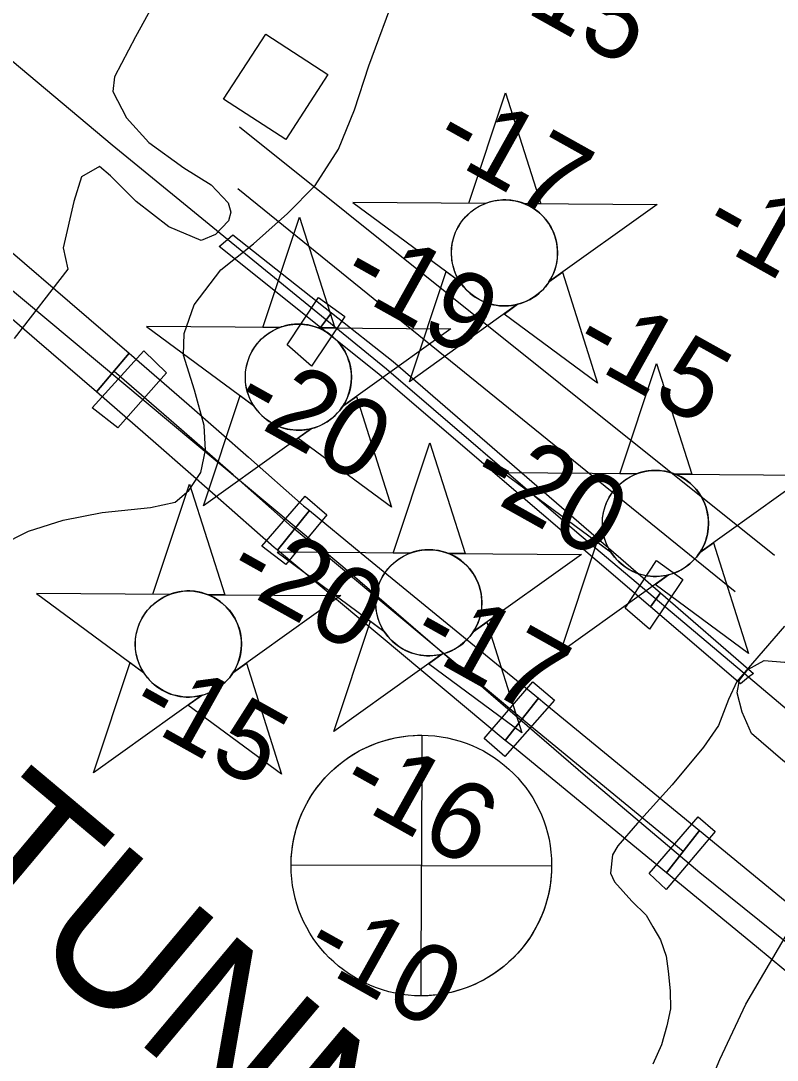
# Model space of a CAD drawing. Extents: x 3683402 to 3721514, y 487807 to 513565.
# Drawn here: x 3700378 to 3700814, y 501053 to 501651 of the extents above; entities that cross this region are included whole.
import ezdxf

# ---------------------------------------------------------------- set-up
doc = ezdxf.new("R2010")
doc.units = 0
for name, color, linetype in [('V-BLDG-OTLN', 7, 'Continuous'), ('V-BRDG-OTLN', 7, 'Continuous'), ('V-CHAN-DOCK', 7, 'Continuous'), ('V-CHAN-NAID', 7, 'Continuous'), ('V-LEVE-TOET', 7, 'Continuous'), ('V-RAIL-TRAK', 7, 'Continuous'), ('V-RIVR-GAGE', 7, 'Continuous'), ('V-ROAD-CNTR', 7, 'Continuous'), ('V-TOPO-GNAM-IDEN', 7, 'Continuous'), ('V-TOPO-SHOR', 7, 'Continuous'), ('V-TOPO-SPOT', 7, 'Continuous'), ('V-UTIL-LINE', 7, 'Continuous')]:
    doc.layers.add(name, color=color, linetype=linetype)

msp = doc.modelspace()

# ---------------------------------------------------------------- linework, layer by layer
at = {"layer": 'V-BLDG-OTLN'}
msp.add_lwpolyline([(3700494.92, 501606.31), (3700519.2, 501643.71), (3700554.98, 501620.48), (3700530.7, 501583.08)], close=True, dxfattribs=at)
at = {"layer": 'V-BRDG-OTLN'}
for points in [[(3700492.35, 501521.52), (3700497.16, 501525.65), (3700500.19, 501528.26), (3700557.09, 501483.31), (3700550.7, 501474.87)], [(3700550.7, 501474.87), (3700557.09, 501483.31), (3700592.49, 501455.36), (3700746.33, 501322.13), (3700740.52, 501314.23), (3700584.47, 501447.87)], [(3700421.7, 501437.84), (3700440.6, 501460.15), (3700475.12, 501430.13), (3700509.29, 501400.21), (3700540.85, 501372.36), (3700544.32, 501369.51), (3700525.89, 501346.66), (3700523.98, 501348.26), (3700489.98, 501378.25), (3700455.9, 501408.1)], [(3700525.89, 501346.66), (3700544.32, 501369.51), (3700574.07, 501345.02), (3700676.09, 501261.53), (3700657, 501237.26)], [(3700740.52, 501314.23), (3700746.33, 501322.13), (3700799.78, 501275.84), (3700796.96, 501273.56), (3700792.34, 501269.85)], [(3700657, 501237.26), (3700676.09, 501261.53), (3700679.76, 501258.52), (3700768.83, 501185.38), (3700749.72, 501161.07), (3700660.14, 501234.63)]]:
    msp.add_lwpolyline(points, close=True, dxfattribs=at)
for points in [[(3700372.01, 501519.15), (3700406.48, 501489.6), (3700440.6, 501460.15), (3700421.7, 501437.84), (3700387.42, 501467.43), (3700353.02, 501496.91)], [(3700759.4, 501173.39), (3700670.08, 501246.74), (3700534.35, 501360.02), (3700500.33, 501390.03), (3700466.21, 501419.91), (3700431.98, 501449.68), (3700431.83, 501449.81)], [(3700919.38, 501020.57), (3700880.2, 501053.24), (3700840.97, 501085.86), (3700801.69, 501118.4), (3700749.72, 501161.07), (3700768.83, 501185.38), (3700821.36, 501142.25), (3700860.71, 501109.65), (3700899.98, 501077), (3700939.2, 501044.29)]]:
    msp.add_lwpolyline(points, dxfattribs=at)
at = {"layer": 'V-CHAN-DOCK'}
for points in [[(3700531.56, 501464.88), (3700549.5, 501492.29), (3700564.66, 501481.28), (3700545.56, 501452.72)], [(3700433.96, 501417.1), (3700419.31, 501428.64), (3700448.93, 501461.42), (3700462.03, 501448.93)], [(3700530.66, 501338.46), (3700516.93, 501349.07), (3700541.89, 501377.78), (3700554.36, 501367.17)], [(3700726.04, 501313.43), (3700743.98, 501340.83), (3700759.14, 501329.83), (3700740.04, 501301.26)], [(3700644.84, 501238.36), (3700672.9, 501271.05), (3700685.37, 501260.44), (3700656.68, 501227.98)], [(3700739.75, 501160.62), (3700768.03, 501193.26), (3700777.81, 501184.78), (3700749.54, 501151.49)]]:
    msp.add_lwpolyline(points, close=True, dxfattribs=at)
at = {"layer": 'V-CHAN-NAID'}
for points in [[(3700645.69, 501546.4), (3700636.1, 501546.47), (3700657.23, 501609.95), (3700677.45, 501546.17), (3700667.86, 501546.24), (3700666.29, 501546.82), (3700664.19, 501547.44), (3700662.15, 501547.89), (3700660.12, 501548.2), (3700658.95, 501548.31), (3700657.42, 501548.39), (3700655.69, 501548.39), (3700654.32, 501548.32), (3700652.42, 501548.12), (3700651.05, 501547.9), (3700649.27, 501547.52), (3700647.74, 501547.1), (3700646.71, 501546.77)], [(3700645.69, 501546.4), (3700569.2, 501546.94), (3700630.76, 501501.54), (3700629.65, 501503.45), (3700628.84, 501505.08), (3700628.01, 501507.05), (3700627.32, 501509.1), (3700626.95, 501510.42), (3700626.59, 501512.05), (3700626.35, 501513.5), (3700626.16, 501515.09), (3700626.05, 501516.83), (3700626.04, 501518.41), (3700626.15, 501520.48), (3700626.33, 501522.1), (3700626.72, 501524.31), (3700627.2, 501526.23), (3700627.81, 501528.12), (3700628.46, 501529.79), (3700629.19, 501531.38), (3700630, 501532.92), (3700631.06, 501534.65), (3700632.09, 501536.12), (3700633.09, 501537.39), (3700634.1, 501538.54), (3700635.4, 501539.88), (3700636.46, 501540.84), (3700638.17, 501542.24), (3700639.38, 501543.11), (3700641.07, 501544.18), (3700642.8, 501545.12), (3700644.25, 501545.81)], [(3700667.86, 501546.24), (3700744.36, 501545.7), (3700682.15, 501501.18), (3700683.06, 501502.67), (3700684.04, 501504.51), (3700684.76, 501506.1), (3700685.5, 501508.05), (3700686.04, 501509.84), (3700686.44, 501511.48), (3700686.8, 501513.49), (3700686.99, 501515.06), (3700687.11, 501517.27), (3700687.08, 501519.33), (3700686.89, 501521.55), (3700686.63, 501523.31), (3700686.14, 501525.54), (3700685.5, 501527.68), (3700684.75, 501529.66), (3700684.1, 501531.1), (3700683.09, 501533.02), (3700682.03, 501534.74), (3700680.81, 501536.44), (3700679.55, 501537.98), (3700678.28, 501539.35), (3700676.65, 501540.88), (3700674.91, 501542.29), (3700673.22, 501543.47), (3700671.34, 501544.6), (3700669.86, 501545.36)], [(3700527.07, 501474.89), (3700517.48, 501474.96), (3700538.61, 501538.44), (3700558.83, 501474.66), (3700549.25, 501474.73), (3700547.67, 501475.31), (3700545.57, 501475.93), (3700543.53, 501476.38), (3700541.5, 501476.69), (3700540.33, 501476.8), (3700538.8, 501476.88), (3700537.08, 501476.88), (3700535.71, 501476.81), (3700533.8, 501476.61), (3700532.43, 501476.39), (3700530.65, 501476.01), (3700529.12, 501475.59), (3700528.09, 501475.26)], [(3700664.12, 501488.27), (3700601.92, 501443.75), (3700623.05, 501507.23), (3700630.76, 501501.54), (3700631.4, 501500.58), (3700632.78, 501498.72), (3700633.99, 501497.3), (3700635.46, 501495.8), (3700636.85, 501494.55), (3700638.3, 501493.39), (3700639.71, 501492.41), (3700641.38, 501491.37), (3700643.1, 501490.46), (3700644.89, 501489.65), (3700646.33, 501489.09), (3700647.96, 501488.56), (3700650.19, 501488), (3700651.72, 501487.71), (3700653.75, 501487.46), (3700655.28, 501487.35), (3700657.14, 501487.33), (3700658.83, 501487.41), (3700660.54, 501487.58), (3700662.44, 501487.89)], [(3700682.15, 501501.18), (3700689.95, 501506.76), (3700710.17, 501442.98), (3700656.33, 501482.69), (3700664.12, 501488.27), (3700665.79, 501488.75), (3700667.4, 501489.31), (3700669.56, 501490.22), (3700671.29, 501491.11), (3700673.16, 501492.22), (3700674.9, 501493.43), (3700676.45, 501494.68), (3700677.74, 501495.84), (3700679.12, 501497.26), (3700680.33, 501498.67), (3700681.44, 501500.14)], [(3700527.07, 501474.89), (3700450.58, 501475.43), (3700512.14, 501430.03), (3700511.03, 501431.94), (3700510.22, 501433.57), (3700509.4, 501435.54), (3700508.7, 501437.59), (3700508.34, 501438.91), (3700507.97, 501440.54), (3700507.73, 501441.98), (3700507.54, 501443.58), (3700507.43, 501445.32), (3700507.42, 501446.9), (3700507.53, 501448.97), (3700507.71, 501450.59), (3700508.1, 501452.79), (3700508.58, 501454.72), (3700509.19, 501456.6), (3700509.84, 501458.28), (3700510.57, 501459.87), (3700511.38, 501461.41), (3700512.44, 501463.14), (3700513.48, 501464.61), (3700514.48, 501465.88), (3700515.48, 501467.03), (3700516.79, 501468.36), (3700517.84, 501469.33), (3700519.55, 501470.73), (3700520.77, 501471.6), (3700522.45, 501472.67), (3700524.18, 501473.61), (3700525.63, 501474.3)], [(3700549.25, 501474.73), (3700625.74, 501474.19), (3700563.54, 501429.67), (3700564.45, 501431.15), (3700565.42, 501433), (3700566.14, 501434.59), (3700566.88, 501436.54), (3700567.42, 501438.33), (3700567.82, 501439.97), (3700568.18, 501441.98), (3700568.37, 501443.55), (3700568.49, 501445.75), (3700568.46, 501447.82), (3700568.27, 501450.04), (3700568.01, 501451.79), (3700567.52, 501454.03), (3700566.88, 501456.17), (3700566.13, 501458.15), (3700565.48, 501459.59), (3700564.47, 501461.51), (3700563.41, 501463.23), (3700562.2, 501464.93), (3700560.94, 501466.47), (3700559.66, 501467.84), (3700558.03, 501469.37), (3700556.29, 501470.78), (3700554.61, 501471.96), (3700552.72, 501473.09), (3700551.25, 501473.85)], [(3700732.56, 501390.7), (3700722.97, 501390.77), (3700744.1, 501454.26), (3700764.32, 501390.48), (3700754.73, 501390.55), (3700753.16, 501391.13), (3700751.06, 501391.75), (3700749.02, 501392.2), (3700746.98, 501392.5), (3700745.82, 501392.62), (3700744.28, 501392.7), (3700742.56, 501392.7), (3700741.19, 501392.63), (3700739.29, 501392.43), (3700737.92, 501392.21), (3700736.14, 501391.82), (3700734.61, 501391.4), (3700733.57, 501391.07)], [(3700545.5, 501416.76), (3700483.3, 501372.24), (3700504.43, 501435.72), (3700512.14, 501430.03), (3700512.78, 501429.07), (3700514.16, 501427.21), (3700515.38, 501425.79), (3700516.84, 501424.29), (3700518.23, 501423.04), (3700519.68, 501421.88), (3700521.09, 501420.89), (3700522.77, 501419.86), (3700524.48, 501418.95), (3700526.27, 501418.14), (3700527.72, 501417.58), (3700529.34, 501417.05), (3700531.57, 501416.49), (3700533.1, 501416.2), (3700535.13, 501415.94), (3700536.66, 501415.84), (3700538.53, 501415.82), (3700540.21, 501415.9), (3700541.92, 501416.07), (3700543.83, 501416.38)], [(3700563.54, 501429.67), (3700571.33, 501435.25), (3700591.56, 501371.47), (3700537.71, 501411.18), (3700545.5, 501416.76), (3700547.17, 501417.24), (3700548.78, 501417.8), (3700550.94, 501418.71), (3700552.68, 501419.59), (3700554.54, 501420.71), (3700556.28, 501421.92), (3700557.83, 501423.16), (3700559.12, 501424.33), (3700560.5, 501425.75), (3700561.71, 501427.15), (3700562.83, 501428.63)], [(3700602.13, 501345.03), (3700592.54, 501345.1), (3700613.67, 501408.59), (3700633.89, 501344.81), (3700624.31, 501344.88), (3700622.73, 501345.46), (3700620.63, 501346.08), (3700618.59, 501346.53), (3700616.56, 501346.83), (3700615.39, 501346.95), (3700613.86, 501347.03), (3700612.14, 501347.03), (3700610.77, 501346.96), (3700608.86, 501346.76), (3700607.49, 501346.54), (3700605.71, 501346.15), (3700604.18, 501345.73), (3700603.15, 501345.4)], [(3700732.56, 501390.7), (3700656.07, 501391.25), (3700717.63, 501345.85), (3700716.52, 501347.76), (3700715.71, 501349.38), (3700714.88, 501351.35), (3700714.19, 501353.41), (3700713.82, 501354.73), (3700713.46, 501356.36), (3700713.22, 501357.8), (3700713.03, 501359.4), (3700712.92, 501361.13), (3700712.91, 501362.72), (3700713.01, 501364.79), (3700713.2, 501366.41), (3700713.59, 501368.61), (3700714.07, 501370.53), (3700714.67, 501372.42), (3700715.33, 501374.1), (3700716.06, 501375.69), (3700716.87, 501377.22), (3700717.93, 501378.96), (3700718.96, 501380.43), (3700719.96, 501381.7), (3700720.96, 501382.84), (3700722.27, 501384.18), (3700723.32, 501385.15), (3700725.04, 501386.54), (3700726.25, 501387.41), (3700727.94, 501388.48), (3700729.67, 501389.43), (3700731.12, 501390.11)], [(3700754.73, 501390.55), (3700831.22, 501390), (3700769.02, 501345.48), (3700769.93, 501346.97), (3700770.91, 501348.82), (3700771.63, 501350.4), (3700772.36, 501352.36), (3700772.91, 501354.14), (3700773.31, 501355.78), (3700773.67, 501357.79), (3700773.85, 501359.37), (3700773.98, 501361.57), (3700773.95, 501363.63), (3700773.76, 501365.85), (3700773.49, 501367.61), (3700773, 501369.84), (3700772.36, 501371.98), (3700771.61, 501373.97), (3700770.97, 501375.41), (3700769.96, 501377.32), (3700768.9, 501379.05), (3700767.68, 501380.75), (3700766.42, 501382.29), (3700765.15, 501383.65), (3700763.52, 501385.19), (3700761.77, 501386.6), (3700760.09, 501387.77), (3700758.2, 501388.91), (3700756.73, 501389.67)], [(3700463.76, 501321.27), (3700454.17, 501321.34), (3700475.3, 501384.82), (3700495.52, 501321.04), (3700485.94, 501321.11), (3700484.36, 501321.69), (3700482.26, 501322.31), (3700480.22, 501322.76), (3700478.19, 501323.07), (3700477.02, 501323.18), (3700475.49, 501323.26), (3700473.76, 501323.26), (3700472.39, 501323.19), (3700470.49, 501322.99), (3700469.12, 501322.77), (3700467.34, 501322.39), (3700465.81, 501321.97), (3700464.78, 501321.64)], [(3700750.99, 501332.58), (3700688.79, 501288.05), (3700709.91, 501351.54), (3700717.63, 501345.85), (3700718.27, 501344.88), (3700719.65, 501343.02), (3700720.86, 501341.61), (3700722.33, 501340.11), (3700723.72, 501338.85), (3700725.17, 501337.7), (3700726.57, 501336.71), (3700728.25, 501335.68), (3700729.97, 501334.76), (3700731.76, 501333.95), (3700733.2, 501333.4), (3700734.83, 501332.87), (3700737.06, 501332.3), (3700738.59, 501332.02), (3700740.61, 501331.76), (3700742.15, 501331.66), (3700744.01, 501331.63), (3700745.7, 501331.71), (3700747.41, 501331.89), (3700749.31, 501332.2)], [(3700769.02, 501345.48), (3700776.82, 501351.06), (3700797.04, 501287.29), (3700743.19, 501327), (3700750.99, 501332.58), (3700752.66, 501333.05), (3700754.27, 501333.61), (3700756.43, 501334.53), (3700758.16, 501335.41), (3700760.03, 501336.52), (3700761.77, 501337.74), (3700763.32, 501338.98), (3700764.61, 501340.15), (3700765.99, 501341.57), (3700767.19, 501342.97), (3700768.31, 501344.44)], [(3700602.13, 501345.03), (3700525.64, 501345.58), (3700587.2, 501300.18), (3700586.09, 501302.09), (3700585.28, 501303.71), (3700584.46, 501305.68), (3700583.76, 501307.74), (3700583.4, 501309.06), (3700583.03, 501310.69), (3700582.79, 501312.13), (3700582.6, 501313.73), (3700582.49, 501315.46), (3700582.48, 501317.05), (3700582.59, 501319.12), (3700582.77, 501320.74), (3700583.16, 501322.94), (3700583.64, 501324.86), (3700584.25, 501326.75), (3700584.9, 501328.43), (3700585.63, 501330.02), (3700586.44, 501331.55), (3700587.5, 501333.29), (3700588.54, 501334.76), (3700589.54, 501336.03), (3700590.54, 501337.17), (3700591.85, 501338.51), (3700592.9, 501339.48), (3700594.61, 501340.87), (3700595.83, 501341.74), (3700597.51, 501342.81), (3700599.24, 501343.76), (3700600.69, 501344.44)], [(3700624.31, 501344.88), (3700700.8, 501344.33), (3700638.6, 501299.81), (3700639.51, 501301.3), (3700640.48, 501303.15), (3700641.2, 501304.73), (3700641.94, 501306.69), (3700642.48, 501308.47), (3700642.88, 501310.11), (3700643.24, 501312.12), (3700643.43, 501313.7), (3700643.55, 501315.9), (3700643.52, 501317.96), (3700643.33, 501320.18), (3700643.07, 501321.94), (3700642.58, 501324.17), (3700641.94, 501326.31), (3700641.19, 501328.3), (3700640.54, 501329.74), (3700639.53, 501331.65), (3700638.47, 501333.38), (3700637.26, 501335.08), (3700636, 501336.62), (3700634.72, 501337.98), (3700633.09, 501339.52), (3700631.35, 501340.93), (3700629.67, 501342.1), (3700627.78, 501343.24), (3700626.31, 501344)], [(3700463.76, 501321.27), (3700387.27, 501321.81), (3700448.83, 501276.41), (3700447.72, 501278.32), (3700446.91, 501279.95), (3700446.09, 501281.92), (3700445.39, 501283.97), (3700445.02, 501285.29), (3700444.66, 501286.92), (3700444.42, 501288.37), (3700444.23, 501289.96), (3700444.12, 501291.7), (3700444.11, 501293.28), (3700444.22, 501295.35), (3700444.4, 501296.97), (3700444.79, 501299.18), (3700445.27, 501301.1), (3700445.88, 501302.99), (3700446.53, 501304.66), (3700447.26, 501306.25), (3700448.07, 501307.79), (3700449.13, 501309.52), (3700450.16, 501310.99), (3700451.16, 501312.26), (3700452.17, 501313.41), (3700453.48, 501314.75), (3700454.53, 501315.71), (3700456.24, 501317.11), (3700457.46, 501317.98), (3700459.14, 501319.05), (3700460.87, 501319.99), (3700462.32, 501320.68)], [(3700485.94, 501321.11), (3700562.43, 501320.57), (3700500.22, 501276.05), (3700501.14, 501277.54), (3700502.11, 501279.38), (3700502.83, 501280.97), (3700503.57, 501282.92), (3700504.11, 501284.71), (3700504.51, 501286.35), (3700504.87, 501288.36), (3700505.06, 501289.93), (3700505.18, 501292.14), (3700505.15, 501294.2), (3700504.96, 501296.42), (3700504.7, 501298.18), (3700504.21, 501300.41), (3700503.57, 501302.55), (3700502.82, 501304.53), (3700502.17, 501305.97), (3700501.16, 501307.89), (3700500.1, 501309.61), (3700498.89, 501311.31), (3700497.62, 501312.85), (3700496.35, 501314.22), (3700494.72, 501315.75), (3700492.98, 501317.16), (3700491.29, 501318.34), (3700489.41, 501319.47), (3700487.94, 501320.23)], [(3700620.56, 501286.91), (3700558.36, 501242.38), (3700579.49, 501305.87), (3700587.2, 501300.18), (3700587.84, 501299.21), (3700589.22, 501297.35), (3700590.44, 501295.94), (3700591.9, 501294.44), (3700593.29, 501293.18), (3700594.74, 501292.03), (3700596.15, 501291.04), (3700597.83, 501290.01), (3700599.54, 501289.09), (3700601.33, 501288.28), (3700602.78, 501287.73), (3700604.4, 501287.2), (3700606.63, 501286.63), (3700608.16, 501286.35), (3700610.19, 501286.09), (3700611.72, 501285.99), (3700613.59, 501285.96), (3700615.27, 501286.04), (3700616.98, 501286.22), (3700618.89, 501286.53)], [(3700638.6, 501299.81), (3700646.39, 501305.39), (3700666.62, 501241.62), (3700612.77, 501281.33), (3700620.56, 501286.91), (3700622.23, 501287.38), (3700623.84, 501287.94), (3700626, 501288.86), (3700627.74, 501289.74), (3700629.6, 501290.85), (3700631.34, 501292.07), (3700632.89, 501293.31), (3700634.18, 501294.48), (3700635.56, 501295.9), (3700636.77, 501297.3), (3700637.89, 501298.77)], [(3700482.19, 501263.14), (3700419.99, 501218.62), (3700441.12, 501282.1), (3700448.83, 501276.41), (3700449.47, 501275.45), (3700450.85, 501273.59), (3700452.06, 501272.17), (3700453.53, 501270.67), (3700454.92, 501269.42), (3700456.37, 501268.26), (3700457.78, 501267.28), (3700459.45, 501266.24), (3700461.17, 501265.33), (3700462.96, 501264.52), (3700464.41, 501263.96), (3700466.03, 501263.43), (3700468.26, 501262.87), (3700469.79, 501262.58), (3700471.82, 501262.33), (3700473.35, 501262.22), (3700475.21, 501262.2), (3700476.9, 501262.28), (3700478.61, 501262.45), (3700480.52, 501262.76)], [(3700500.22, 501276.05), (3700508.02, 501281.63), (3700528.24, 501217.85), (3700474.4, 501257.56), (3700482.19, 501263.14), (3700483.86, 501263.62), (3700485.47, 501264.18), (3700487.63, 501265.09), (3700489.36, 501265.98), (3700491.23, 501267.09), (3700492.97, 501268.3), (3700494.52, 501269.55), (3700495.81, 501270.71), (3700497.19, 501272.13), (3700498.4, 501273.54), (3700499.52, 501275.01)]]:
    msp.add_lwpolyline(points, close=True, dxfattribs=at)
for centre in [(3700656.57, 501517.86), (3700537.96, 501446.35), (3700743.44, 501362.17), (3700613.02, 501316.5), (3700474.64, 501292.74)]:
    msp.add_circle(centre, 30.54, dxfattribs=at)
at = {"layer": 'V-LEVE-TOET'}
for points in [[(3700773.66, 501037.06), (3700780.42, 501053.65), (3700795.41, 501085.36), (3700829.8, 501143.94), (3700850.12, 501182), (3700848.13, 501195.15), (3700837.36, 501210.7), (3700816.85, 501225.73), (3700798.77, 501241.26), (3700793.37, 501253.42), (3700790.41, 501264.61), (3700791.86, 501271.93), (3700796.56, 501278.07), (3700805.94, 501283.18), (3700817.63, 501282.24), (3700837.62, 501275.49), (3700858.13, 501263.38), (3700874.23, 501254.67), (3700886.39, 501260.07), (3700898.52, 501275.7), (3700941.07, 501365.97), (3701009.36, 501481.17), (3701075.15, 501616.33), (3701142.42, 501744.68)], [(3700496.95, 501741.56), (3700468.18, 501686.01), (3700444.28, 501642.24), (3700432.1, 501619.14), (3700431.14, 501610.79), (3700439.05, 501595.6), (3700451.86, 501581.42), (3700472.03, 501566.76), (3700487.77, 501557), (3700497.62, 501546.73), (3700499.11, 501541.34), (3700497.65, 501536.42), (3700490.32, 501528.55), (3700481.99, 501525.08), (3700463.31, 501532.87), (3700444.61, 501547.53), (3700429.84, 501562.2), (3700423.44, 501567.58), (3700413.15, 501561.65), (3700408.78, 501547.4), (3700402.5, 501520.88), (3700405.21, 501508.46)], [(3700405.21, 501508.46), (3700374.43, 501468.6)]]:
    msp.add_lwpolyline(points, dxfattribs=at)
at = {"layer": 'V-RAIL-TRAK'}
msp.add_line((3700588.63, 501450.87), (3700497.16, 501525.65), dxfattribs=at)
for points in [[(3700497.16, 501525.65), (3700430.85, 501579.85), (3700214.77, 501761.35)], [(3700796.96, 501273.56), (3700698.14, 501357.01), (3700588.63, 501450.87)], [(3702449.04, 499884.6), (3702448.85, 499884.75), (3702313.95, 499999.7), (3702089.55, 500187.39), (3701884.71, 500359.38), (3701706.93, 500508.63), (3701550.8, 500639.69), (3701346.38, 500811.27), (3701273.52, 500872.87), (3701261.43, 500883.06), (3701232.3, 500907.6), (3700970.85, 501126.72), (3700889.43, 501195.48), (3700796.96, 501273.56)]]:
    msp.add_lwpolyline(points, dxfattribs=at)
at = {"layer": 'V-RIVR-GAGE'}
for points in [[(3700608.9, 501240.21), (3700608.71, 501165.21), (3700533.71, 501165.39), (3700533.75, 501167.5), (3700533.87, 501170.07), (3700534.12, 501173.06), (3700534.49, 501176.02), (3700534.95, 501178.79), (3700535.56, 501181.76), (3700536.19, 501184.34), (3700536.86, 501186.71), (3700537.63, 501189.12), (3700538.6, 501191.85), (3700539.54, 501194.2), (3700540.55, 501196.5), (3700541.75, 501198.99), (3700543.19, 501201.7), (3700544.54, 501204.03), (3700545.94, 501206.26), (3700548.35, 501209.73), (3700550.05, 501211.95), (3700552.28, 501214.61), (3700554.43, 501216.97), (3700556.27, 501218.83), (3700559.05, 501221.41), (3700561.39, 501223.4), (3700563.85, 501225.31), (3700566.97, 501227.52), (3700569.35, 501229.05), (3700571.94, 501230.58), (3700574.92, 501232.17), (3700577.56, 501233.43), (3700580.16, 501234.56), (3700583.79, 501235.95), (3700587.03, 501237.01), (3700590.21, 501237.89), (3700593.47, 501238.64), (3700596.87, 501239.27), (3700600.92, 501239.8), (3700603.91, 501240.05), (3700606.46, 501240.17)], [(3700608.52, 501090.21), (3700608.71, 501165.21), (3700683.71, 501165.02), (3700683.66, 501162.37), (3700683.47, 501159.21), (3700683.22, 501156.62), (3700682.87, 501154.01), (3700682.33, 501150.89), (3700681.68, 501147.89), (3700680.82, 501144.57), (3700680.17, 501142.43), (3700679.19, 501139.58), (3700678.07, 501136.66), (3700676.97, 501134.12), (3700675.78, 501131.63), (3700674.49, 501129.18), (3700673.15, 501126.83), (3700671.5, 501124.19), (3700670, 501121.98), (3700667.88, 501119.12), (3700665.73, 501116.49), (3700663.1, 501113.57), (3700660.81, 501111.25), (3700658.32, 501108.96), (3700656.13, 501107.1), (3700654.49, 501105.8), (3700651.83, 501103.84), (3700649.92, 501102.54), (3700647.4, 501100.96), (3700644.74, 501099.43), (3700642.02, 501098.01), (3700639.89, 501097), (3700637.62, 501096), (3700635, 501094.97), (3700632.29, 501094.01), (3700629.02, 501093.01), (3700625.86, 501092.19), (3700623.43, 501091.66), (3700620.67, 501091.17), (3700618.28, 501090.82), (3700615.49, 501090.51), (3700613.3, 501090.35), (3700610.73, 501090.23)]]:
    msp.add_lwpolyline(points, close=True, dxfattribs=at)
msp.add_circle((3700608.71, 501165.21), 75, dxfattribs=at)
at = {"layer": 'V-ROAD-CNTR'}
msp.add_lwpolyline([(3702238.98, 500002.6), (3701998.05, 500198.72), (3701875.21, 500297.92), (3701767.12, 500387.66), (3701606.08, 500515.54), (3701489.32, 500611.09), (3701364.19, 500717.81), (3701316.38, 500761.93), (3701239.27, 500821.23), (3701163.5, 500873.2), (3701061.3, 500943.14), (3700941.81, 501026.47), (3700845.53, 501099.41), (3700768.93, 501161.06), (3700704.49, 501215.5), (3700563.51, 501337.24), (3700365.05, 501502.97), (3700205.58, 501635.76), (3700064.58, 501755.85), (3699929.63, 501868.81), (3699805.36, 501967.03), (3699552.33, 502184.74), (3699273.81, 502419.23)], dxfattribs=at)
at = {"layer": 'V-TOPO-SHOR'}
for points in [[(3700366.12, 501349.38), (3700382.59, 501357.69), (3700402.6, 501364.04), (3700424.98, 501368.44), (3700452.86, 501371.29), (3700466.99, 501374.48), (3700474.83, 501381.18), (3700481.86, 501391.42), (3700484.57, 501404.39), (3700483.73, 501418.53), (3700478.16, 501438.94), (3700471.81, 501458.95), (3700472.16, 501471.53), (3700477.99, 501488.04), (3700493.24, 501508.13), (3700512.05, 501523.12), (3700531.63, 501540.48), (3700547.68, 501556.64), (3700560.96, 501577.5), (3700570.31, 501600.32), (3700578.48, 501625.49), (3700594.43, 501668.75)], [(3700817.64, 501303.01), (3700799.25, 501281.74), (3700790.25, 501271.1), (3700785.58, 501260.87), (3700779.73, 501245.92), (3700771.14, 501233.32), (3700753.14, 501211.66), (3700733.18, 501189.59), (3700721.83, 501176.59), (3700718.71, 501171.47), (3700717.57, 501160.86), (3700719.94, 501155.76), (3700729.8, 501144.79), (3700738.08, 501136.57), (3700742.03, 501129.91), (3700746.38, 501122.46), (3700749.55, 501113.04), (3700750.76, 501104.41), (3700751.98, 501093.02), (3700752.01, 501082.8), (3700750.08, 501072.98), (3700746.98, 501061.97), (3700741.91, 501050.95)]]:
    msp.add_lwpolyline(points, dxfattribs=at)
at = {"layer": 'V-UTIL-LINE'}
for p, q in [((3700503.97, 501590.45), (3700812.04, 501343.89)), ((3700503.02, 501554.98), (3700789.31, 501322.93))]:
    msp.add_line(p, q, dxfattribs=at)

# ---------------------------------------------------------------- texts
at = {"layer": 'V-TOPO-GNAM-IDEN'}
msp.add_text('TUNNEL', height=83, rotation=320, dxfattribs=at).set_placement((3700328.93, 501161.35))
at = {"layer": 'V-TOPO-SPOT'}
for s, p in [('-15', (3700650.53, 501666.71)), ('-17', (3700613.36, 501577.4)), ('-11', (3700768.27, 501527.91)), ('-19', (3700560.06, 501499.03)), ('-15', (3700693.59, 501459.89)), ('-20', (3700498.4, 501426.74)), ('-20', (3700634.36, 501383.4)), ('-20', (3700494.41, 501329.45)), ('-17', (3700600.17, 501292.07)), ('-15', (3700438.4, 501251.33)), ('-16', (3700559.53, 501206.26)), ('-10', (3700538.99, 501112.4))]:
    msp.add_text(s, height=45, rotation=330.79328, dxfattribs=at).set_placement(p)

doc.saveas('drawing.dxf')
